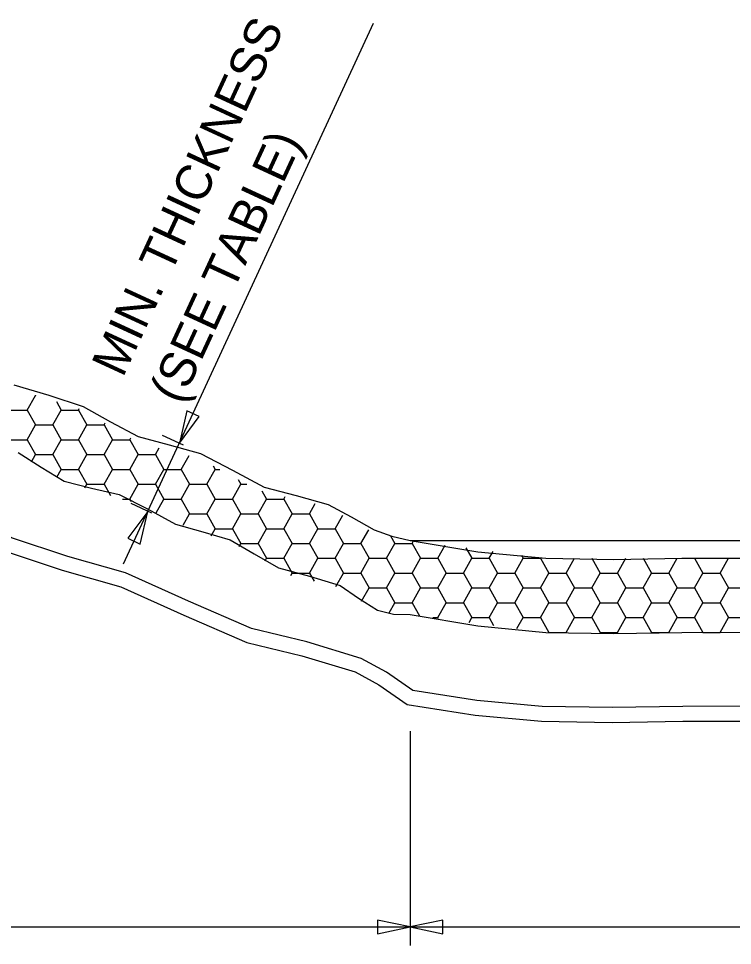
# Model space of a CAD drawing. Extents: x -439.1 to -407.9, y -458.1 to -436.2.
# Drawn here: x -431.292 to -428.281, y -452.73 to -448.82 of the extents above; entities that cross this region are included whole.
import ezdxf

# ---------------------------------------------------------------- set-up
doc = ezdxf.new("R2010")
doc.units = 0
doc.layers.add('Default', color=7, linetype='Continuous')

msp = doc.modelspace()

# ---------------------------------------------------------------- linework, layer by layer
at = {"layer": 'Default'}
for p, q in [((-430.8489, -451.1204), (-429.7951, -448.8389)), ((-431.2563, -450.4719), (-431.2202, -450.4094)), ((-431.2203, -450.4093), (-431.2202, -450.4094)), ((-431.2202, -450.4094), (-431.2197, -450.4094)), ((-431.1326, -450.4361), (-431.1119, -450.4719)), ((-431.3284, -450.4719), (-431.2563, -450.4719)), ((-431.2563, -450.4719), (-431.2202, -450.5344)), ((-431.148, -450.5344), (-431.1119, -450.4719)), ((-431.1119, -450.4719), (-431.0398, -450.4719)), ((-431.0398, -450.4719), (-431.0361, -450.4656)), ((-431.0397, -450.4719), (-431.0037, -450.5344)), ((-431.2563, -450.5969), (-431.2202, -450.5344)), ((-431.2202, -450.5344), (-431.148, -450.5344)), ((-431.148, -450.5344), (-431.1119, -450.5969)), ((-431.0398, -450.5969), (-431.0037, -450.5344)), ((-431.0037, -450.5344), (-430.9315, -450.5344)), ((-430.9315, -450.5344), (-430.9265, -450.5257)), ((-430.9315, -450.5344), (-430.8954, -450.5969)), ((-431.3284, -450.5969), (-431.2563, -450.5969)), ((-431.2563, -450.5969), (-431.2202, -450.6594)), ((-431.148, -450.6594), (-431.1119, -450.5969)), ((-431.1119, -450.5969), (-431.0398, -450.5969)), ((-431.0398, -450.5969), (-431.0037, -450.6594)), ((-430.9315, -450.6594), (-430.8954, -450.5969)), ((-430.8954, -450.5969), (-430.8232, -450.5969)), ((-430.8232, -450.5969), (-430.8186, -450.5889)), ((-430.8232, -450.5969), (-430.7872, -450.6594)), ((-430.5971, -450.6196), (-430.6849, -450.5791)), ((-430.715, -450.6594), (-430.6985, -450.6309)), ((-431.2376, -450.6896), (-431.2202, -450.6594)), ((-431.2202, -450.6594), (-431.148, -450.6594)), ((-431.148, -450.6594), (-431.1119, -450.7219)), ((-431.0398, -450.7219), (-431.0037, -450.6594)), ((-431.0037, -450.6594), (-430.9315, -450.6594)), ((-430.9315, -450.6594), (-430.8954, -450.7219)), ((-430.8232, -450.7219), (-430.7872, -450.6594)), ((-430.7872, -450.6594), (-430.715, -450.6594)), ((-430.715, -450.6594), (-430.6789, -450.7219)), ((-430.6067, -450.7219), (-430.5725, -450.6626)), ((-430.4712, -450.7068), (-430.4624, -450.7219)), ((-431.1311, -450.7551), (-431.1119, -450.7219)), ((-431.1119, -450.7219), (-431.0398, -450.7219)), ((-431.0398, -450.7219), (-431.0037, -450.7844)), ((-430.9315, -450.7844), (-430.8954, -450.7219)), ((-430.8954, -450.7219), (-430.8232, -450.7219)), ((-430.8232, -450.7219), (-430.7872, -450.7844)), ((-430.715, -450.7844), (-430.6789, -450.7219)), ((-430.6789, -450.7219), (-430.6067, -450.7219)), ((-430.6067, -450.7219), (-430.5706, -450.7844)), ((-430.4985, -450.7844), (-430.4624, -450.7219)), ((-430.4624, -450.7219), (-430.4435, -450.7219)), ((-431.0124, -450.7995), (-431.0037, -450.7844)), ((-431.0037, -450.7844), (-430.9315, -450.7844)), ((-430.9315, -450.7844), (-430.9041, -450.8319)), ((-430.8232, -450.8469), (-430.7872, -450.7844)), ((-430.7872, -450.7844), (-430.715, -450.7844)), ((-430.715, -450.7844), (-430.6789, -450.8469)), ((-430.6067, -450.8469), (-430.5706, -450.7844)), ((-430.5706, -450.7844), (-430.4985, -450.7844)), ((-430.4985, -450.7844), (-430.4624, -450.8469)), ((-430.3902, -450.8469), (-430.3541, -450.7844)), ((-430.3656, -450.7646), (-430.3541, -450.7844)), ((-430.3541, -450.7844), (-430.3294, -450.7844)), ((-430.2659, -450.8123), (-430.2459, -450.8469)), ((-430.8537, -450.8469), (-430.8232, -450.8469)), ((-430.8232, -450.8469), (-430.8169, -450.8579)), ((-430.7298, -450.9069), (-430.8176, -450.8663)), ((-430.7124, -450.9049), (-430.6789, -450.8469)), ((-430.6789, -450.8469), (-430.6067, -450.8469)), ((-430.6067, -450.8469), (-430.5706, -450.9094)), ((-430.4985, -450.9094), (-430.4624, -450.8469)), ((-430.4624, -450.8469), (-430.3902, -450.8469)), ((-430.3902, -450.8469), (-430.3541, -450.9094)), ((-430.282, -450.9094), (-430.2459, -450.8469)), ((-430.2459, -450.8469), (-430.1737, -450.8469)), ((-430.1737, -450.8469), (-430.1674, -450.8359)), ((-430.1737, -450.8469), (-430.1376, -450.9094)), ((-430.0655, -450.9094), (-430.0406, -450.8663)), ((-430.5979, -450.9567), (-430.5706, -450.9094)), ((-430.5706, -450.9094), (-430.4985, -450.9094)), ((-430.4985, -450.9094), (-430.4624, -450.9719)), ((-430.3902, -450.9719), (-430.3541, -450.9094)), ((-430.3541, -450.9094), (-430.282, -450.9094)), ((-430.282, -450.9094), (-430.2459, -450.9719)), ((-430.1737, -450.9719), (-430.1376, -450.9094)), ((-430.1376, -450.9094), (-430.0655, -450.9094)), ((-430.0655, -450.9094), (-430.0294, -450.9719)), ((-429.9572, -450.9719), (-429.9242, -450.9147)), ((-430.4799, -451.0022), (-430.4624, -450.9719)), ((-430.4624, -450.9719), (-430.3902, -450.9719)), ((-430.3902, -450.9719), (-430.3541, -451.0344)), ((-430.282, -451.0344), (-430.2459, -450.9719)), ((-430.2459, -450.9719), (-430.1737, -450.9719)), ((-430.1737, -450.9719), (-430.1376, -451.0344)), ((-430.0655, -451.0344), (-430.0294, -450.9719)), ((-430.0294, -450.9719), (-429.9572, -450.9719)), ((-429.9572, -450.9719), (-429.9211, -451.0344)), ((-429.849, -451.0344), (-429.8153, -450.9761)), ((-429.7234, -451.0019), (-429.7046, -451.0344)), ((-429.6399, -451.0216), (-426.2024, -451.0216)), ((-429.6325, -451.0344), (-429.6263, -451.0238)), ((-430.3613, -451.0468), (-430.3541, -451.0344)), ((-430.3541, -451.0344), (-430.282, -451.0344)), ((-430.282, -451.0344), (-430.2459, -451.0969)), ((-430.1737, -451.0969), (-430.1376, -451.0344)), ((-430.1376, -451.0344), (-430.0655, -451.0344)), ((-430.0655, -451.0344), (-430.0294, -451.0969)), ((-429.9572, -451.0969), (-429.9211, -451.0344)), ((-429.9211, -451.0344), (-429.849, -451.0344)), ((-429.849, -451.0344), (-429.8129, -451.0969)), ((-429.7407, -451.0969), (-429.7046, -451.0344)), ((-429.7046, -451.0344), (-429.6404, -451.0344)), ((-429.6404, -451.0344), (-429.6325, -451.0344)), ((-429.6325, -451.0344), (-429.5964, -451.0969)), ((-429.5242, -451.0969), (-429.4921, -451.0414)), ((-429.4054, -451.0527), (-429.3799, -451.0969)), ((-429.3077, -451.0969), (-429.2908, -451.0677)), ((-430.2519, -451.1073), (-430.2459, -451.0969)), ((-430.2459, -451.0969), (-430.1737, -451.0969)), ((-430.1737, -451.0969), (-430.1376, -451.1594)), ((-430.0655, -451.1594), (-430.0294, -451.0969)), ((-430.0294, -451.0969), (-429.9572, -451.0969)), ((-429.9572, -451.0969), (-429.9211, -451.1594)), ((-429.849, -451.1594), (-429.8129, -451.0969)), ((-429.8129, -451.0969), (-429.7407, -451.0969)), ((-429.7407, -451.0969), (-429.7046, -451.1594)), ((-429.6325, -451.1594), (-429.5964, -451.0969)), ((-429.5964, -451.0969), (-429.5242, -451.0969)), ((-429.5242, -451.0969), (-429.4881, -451.1594)), ((-429.4159, -451.1594), (-429.3799, -451.0969)), ((-429.3799, -451.0969), (-429.3077, -451.0969)), ((-429.3077, -451.0969), (-429.2716, -451.1594)), ((-429.1994, -451.1594), (-429.1634, -451.0969)), ((-429.1712, -451.0834), (-429.1634, -451.0969)), ((-429.1634, -451.0969), (-429.0912, -451.0969)), ((-429.0912, -451.0969), (-429.0895, -451.0941)), ((-429.0912, -451.0969), (-429.0551, -451.1594)), ((-428.9829, -451.1594), (-428.9469, -451.0969)), ((-428.8747, -451.0969), (-428.8386, -451.1594)), ((-428.7664, -451.1594), (-428.7304, -451.0969)), ((-428.6582, -451.0969), (-428.6221, -451.1594)), ((-428.5499, -451.1594), (-428.5139, -451.0969)), ((-428.4417, -451.0969), (-428.4056, -451.1594)), ((-428.3334, -451.1594), (-428.2974, -451.0969)), ((-430.1437, -451.1699), (-430.1376, -451.1594)), ((-430.1376, -451.1594), (-430.0655, -451.1594)), ((-430.0655, -451.1594), (-430.0459, -451.1933)), ((-429.9535, -451.2155), (-429.9211, -451.1594)), ((-429.9211, -451.1594), (-429.849, -451.1594)), ((-429.849, -451.1594), (-429.8129, -451.2219)), ((-429.7407, -451.2219), (-429.7046, -451.1594)), ((-429.7046, -451.1594), (-429.6404, -451.1594)), ((-429.6404, -451.1594), (-429.6325, -451.1594)), ((-429.6325, -451.1594), (-429.5964, -451.2219)), ((-429.5242, -451.2219), (-429.4881, -451.1594)), ((-429.4881, -451.1594), (-429.4159, -451.1594)), ((-429.4159, -451.1594), (-429.3799, -451.2219)), ((-429.3077, -451.2219), (-429.2716, -451.1594)), ((-429.2716, -451.1594), (-429.1994, -451.1594)), ((-429.1994, -451.1594), (-429.1634, -451.2219)), ((-429.0912, -451.2219), (-429.0551, -451.1594)), ((-429.0551, -451.1594), (-428.9829, -451.1594)), ((-428.9829, -451.1594), (-428.9469, -451.2219)), ((-428.8747, -451.2219), (-428.8386, -451.1594)), ((-428.8386, -451.1594), (-428.7664, -451.1594)), ((-428.7664, -451.1594), (-428.7303, -451.2219)), ((-428.6582, -451.2219), (-428.6221, -451.1594)), ((-428.6221, -451.1594), (-428.5499, -451.1594)), ((-428.5499, -451.1594), (-428.5138, -451.2219)), ((-428.4417, -451.2219), (-428.4056, -451.1594)), ((-428.4056, -451.1594), (-428.3334, -451.1594)), ((-428.3334, -451.1594), (-428.2973, -451.2219)), ((-429.845, -451.2775), (-429.8129, -451.2219)), ((-429.8129, -451.2219), (-429.7407, -451.2219)), ((-429.7407, -451.2219), (-429.7046, -451.2844)), ((-429.6325, -451.2844), (-429.5964, -451.2219)), ((-429.5964, -451.2219), (-429.5242, -451.2219)), ((-429.5242, -451.2219), (-429.4881, -451.2844)), ((-429.4159, -451.2844), (-429.3799, -451.2219)), ((-429.3799, -451.2219), (-429.3077, -451.2219)), ((-429.3077, -451.2219), (-429.2716, -451.2844)), ((-429.1994, -451.2844), (-429.1634, -451.2219)), ((-429.1634, -451.2219), (-429.0912, -451.2219)), ((-429.0912, -451.2219), (-429.0551, -451.2844)), ((-428.9829, -451.2844), (-428.9469, -451.2219)), ((-428.9469, -451.2219), (-428.8747, -451.2219)), ((-428.8747, -451.2219), (-428.8386, -451.2844)), ((-428.7664, -451.2844), (-428.7303, -451.2219)), ((-428.7303, -451.2219), (-428.6582, -451.2219)), ((-428.6582, -451.2219), (-428.6221, -451.2844)), ((-428.5499, -451.2844), (-428.5138, -451.2219)), ((-428.5138, -451.2219), (-428.4417, -451.2219)), ((-428.4417, -451.2219), (-428.4056, -451.2844)), ((-428.3334, -451.2844), (-428.2973, -451.2219)), ((-428.2973, -451.2219), (-428.2252, -451.2219)), ((-429.7289, -451.3265), (-429.7046, -451.2844)), ((-429.7046, -451.2844), (-429.6404, -451.2844)), ((-429.6404, -451.2844), (-429.6325, -451.2844)), ((-429.6325, -451.2844), (-429.6006, -451.3397)), ((-429.5242, -451.3469), (-429.4881, -451.2844)), ((-429.4881, -451.2844), (-429.4159, -451.2844)), ((-429.4159, -451.2844), (-429.3799, -451.3469)), ((-429.3077, -451.3469), (-429.2716, -451.2844)), ((-429.2716, -451.2844), (-429.1994, -451.2844)), ((-429.1994, -451.2844), (-429.1634, -451.3469)), ((-429.0912, -451.3469), (-429.0551, -451.2844)), ((-429.0551, -451.2844), (-428.9829, -451.2844)), ((-428.9829, -451.2844), (-428.9469, -451.3469)), ((-428.8747, -451.3469), (-428.8386, -451.2844)), ((-428.8386, -451.2844), (-428.7664, -451.2844)), ((-428.7664, -451.2844), (-428.7303, -451.3469)), ((-428.6582, -451.3469), (-428.6221, -451.2844)), ((-428.6221, -451.2844), (-428.5499, -451.2844)), ((-428.5499, -451.2844), (-428.5138, -451.3469)), ((-428.4417, -451.3469), (-428.4056, -451.2844)), ((-428.4056, -451.2844), (-428.3334, -451.2844)), ((-428.3334, -451.2844), (-428.2973, -451.3469)), ((-429.5452, -451.3469), (-429.5242, -451.3469)), ((-429.5242, -451.3469), (-429.5225, -451.3499)), ((-429.3915, -451.367), (-429.3799, -451.3469)), ((-429.3799, -451.3469), (-429.3077, -451.3469)), ((-429.3077, -451.3469), (-429.2883, -451.3805)), ((-429.1902, -451.3934), (-429.1634, -451.3469)), ((-429.1634, -451.3469), (-429.0912, -451.3469)), ((-429.0912, -451.3469), (-429.0551, -451.4094)), ((-428.9829, -451.4094), (-428.9469, -451.3469)), ((-428.9469, -451.3469), (-428.8747, -451.3469)), ((-428.8747, -451.3469), (-428.8386, -451.4094)), ((-428.7664, -451.4094), (-428.7303, -451.3469)), ((-428.7303, -451.3469), (-428.6582, -451.3469)), ((-428.6582, -451.3469), (-428.6221, -451.4094)), ((-428.5499, -451.4094), (-428.5138, -451.3469)), ((-428.5138, -451.3469), (-428.4417, -451.3469)), ((-428.4417, -451.3469), (-428.4056, -451.4094)), ((-428.3334, -451.4094), (-428.2973, -451.3469)), ((-428.2973, -451.3469), (-428.2252, -451.3469)), ((-429.0551, -451.4094), (-428.9829, -451.4094)), ((-429.0551, -451.4094), (-429.0551, -451.4094)), ((-428.9829, -451.4094), (-428.9829, -451.4094)), ((-428.8386, -451.4094), (-428.7664, -451.4094)), ((-428.8386, -451.4094), (-428.8386, -451.4094)), ((-428.7664, -451.4094), (-428.7664, -451.4094)), ((-428.6221, -451.4094), (-428.5499, -451.4094)), ((-428.6221, -451.4094), (-428.6221, -451.4094)), ((-428.5499, -451.4094), (-428.5499, -451.4094)), ((-428.4056, -451.4094), (-428.3334, -451.4094)), ((-428.4056, -451.4094), (-428.4056, -451.4094)), ((-428.3334, -451.4094), (-428.3334, -451.4094)), ((-429.6404, -451.8256), (-429.6404, -452.73)), ((-435.0126, -452.6519), (-429.6404, -452.6519)), ((-429.6404, -452.6519), (-426.2029, -452.6519))]:
    msp.add_line(p, q, dxfattribs=at)
for points in [[(-429.6296, -451.6546), (-429.74, -451.5769), (-429.8464, -451.5189), (-430.0756, -451.4499), (-430.31, -451.3931), (-430.5758, -451.2778), (-430.8406, -451.1579), (-431.0844, -451.0895), (-431.322, -451.0102), (-431.4567, -450.9324), (-431.5851, -450.8409), (-431.714, -450.7506), (-431.8499, -450.6765), (-431.9989, -450.628), (-432.1549, -450.5944), (-432.4503, -450.5204), (-432.5894, -450.4621), (-432.7184, -450.3797), (-432.818, -450.2973), (-432.8699, -450.2635), (-432.9262, -450.2429), (-433.0022, -450.2413), (-433.0779, -450.2591)], [(-433.0672, -450.3206), (-432.998, -450.3037), (-432.9386, -450.3042), (-432.8896, -450.3229), (-432.8447, -450.3538), (-432.7571, -450.4288), (-432.6223, -450.5152), (-432.4767, -450.577), (-432.1673, -450.6557), (-432.0175, -450.6876), (-431.8746, -450.7339), (-431.7392, -450.8078), (-431.6108, -450.8979), (-431.4828, -450.9892), (-431.3486, -451.0667), (-431.1081, -451.1473), (-430.8615, -451.2168), (-430.5957, -451.337), (-430.329, -451.4527), (-430.0979, -451.5083), (-429.8719, -451.576), (-429.7719, -451.6306), (-429.6536, -451.7141)], [(-431.3126, -450.3658), (-431.1648, -450.4087), (-431.0191, -450.4559), (-430.9042, -450.5205), (-430.7884, -450.5824), (-430.6564, -450.6186), (-430.5242, -450.6542), (-430.3902, -450.7257), (-430.2561, -450.7969), (-430.121, -450.8324), (-429.9869, -450.8698), (-429.8891, -450.9226), (-429.7916, -450.9771), (-429.7173, -451.0037), (-429.6404, -451.0219)], [(-431.2933, -450.6512), (-431.1969, -450.7119), (-431.1, -450.7716), (-430.9847, -450.8015), (-430.8673, -450.8273), (-430.7485, -450.8886), (-430.6305, -450.9528), (-430.5146, -450.9848), (-430.3998, -451.0186), (-430.2983, -451.0782), (-430.1963, -451.1369), (-430.0648, -451.1716), (-429.9363, -451.2118), (-429.8583, -451.2654), (-429.7784, -451.3151), (-429.7109, -451.3319), (-429.6404, -451.3344)], [(-429.6404, -451.0219), (-429.3552, -451.0697), (-429.0675, -451.0969), (-428.7812, -451.1016), (-428.4946, -451.0969), (-428.2081, -451.096), (-427.9217, -451.0969), (-427.6353, -451.096), (-427.3487, -451.0969), (-427.0621, -451.1016), (-426.7758, -451.0969), (-426.4881, -451.0697), (-426.2029, -451.0219)], [(-429.6404, -451.3344), (-429.3552, -451.3822), (-429.0675, -451.4094), (-428.7812, -451.4141), (-428.4946, -451.4094), (-428.2081, -451.4085), (-427.9217, -451.4094), (-427.6353, -451.4085), (-427.3487, -451.4094), (-427.0621, -451.4141), (-426.7758, -451.4094), (-426.4881, -451.3822), (-426.2029, -451.3344)], [(-426.2155, -451.655), (-426.4866, -451.6971), (-426.7596, -451.7215), (-427.056, -451.7265), (-427.3528, -451.7219), (-427.6373, -451.721), (-427.9217, -451.7219), (-428.206, -451.721), (-428.4905, -451.7219), (-428.7873, -451.7265), (-429.0837, -451.7215), (-429.3591, -451.6968), (-429.6296, -451.6546)], [(-429.6536, -451.7141), (-429.3663, -451.7589), (-429.087, -451.7839), (-428.7885, -451.789), (-428.4897, -451.7844), (-428.2056, -451.7835), (-427.9217, -451.7844), (-427.6377, -451.7835), (-427.3536, -451.7844), (-427.0548, -451.789), (-426.7563, -451.7839), (-426.4794, -451.7592), (-426.2044, -451.7165)]]:
    msp.add_lwpolyline(points, dxfattribs=at)
for points in [[(-430.5821, -450.4742), (-430.614, -450.6118), (-430.5299, -450.4983)], [(-430.5821, -450.4742), (-430.614, -450.6118), (-430.5299, -450.4983)], [(-430.7786, -451.0367), (-430.7467, -450.8991), (-430.8307, -451.0126)], [(-430.7786, -451.0367), (-430.7467, -450.8991), (-430.8307, -451.0126)], [(-429.7787, -452.6806), (-429.6404, -452.6519), (-429.7787, -452.6232)], [(-429.5021, -452.6232), (-429.6404, -452.6519), (-429.5021, -452.6806)]]:
    msp.add_lwpolyline(points, close=True, dxfattribs=at)

# ---------------------------------------------------------------- texts
for s, p in [('MIN. THICKNESS ', (-430.8525, -450.3385)), ('(SEE TABLE)', (-430.6074, -450.4517))]:
    msp.add_text(s, height=0.15, rotation=65.2, dxfattribs=at).set_placement(p)

doc.saveas('drawing.dxf')
